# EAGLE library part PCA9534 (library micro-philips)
8-bit I2C-bus and SMBus low power I/O port with interrupt Source: www.nxp.com .. PCA9534_3.pdf
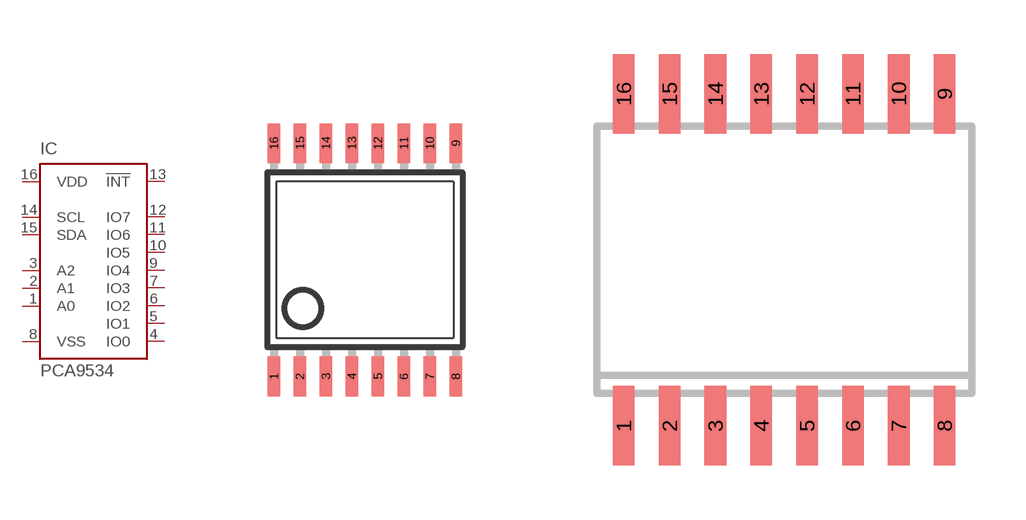
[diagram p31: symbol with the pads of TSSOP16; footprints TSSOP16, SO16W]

Designator prefix IC

## PCA9534PW (MPN: PCA9534PW; OC_FARNELL: 1408285; OC_NEWARK: 18M7516)  [TSSOP16]
1  A0  in
2  A1  in
3  A2  in
4  IO0
5  IO1
6  IO2
7  IO3
8  VSS  pwr
9  IO4
10  IO5
11  IO6
12  IO7
13  !INT  oc
14  SCL  in
15  SDA
16  VDD  pwr

## PCA9534D (MPN: PCA9534DB; OC_FARNELL: 1408284; OC_NEWARK: 18M7513)  [SO16W]
Pads as for TSSOP16

## PCA9534BS (MPN: PCA9534BS,118; OC_FARNELL: unknown; OC_NEWARK: 70R6525)  [HVQFN16_4X4]
1  A2  in
2  IO0
3  IO1
4  IO2
5  IO3
6  VSS  pwr
7  IO4
8  IO5
9  IO6
10  IO7
11  !INT  oc
12  SCL  in
13  SDA
14  VDD  pwr
15  A0  in
16  A1  in

## PCA9534BS3 (MPN: PCA9534BS3,118; OC_FARNELL: unknown; OC_NEWARK: 70R6526)  [HVQFN16_3X3]
Pads as for HVQFN16_4X4

## Footprint TSSOP16 (pad centres in mm)
TSSOP16: plastic thin shrink small outline package; 16 leads; body width 4.4 mm SOT403-1 Source: PCA9534_3.pdf
smd 0.305 x 0.991: 1 -2.275,-2.918; 2 -1.625,-2.918; 3 -0.975,-2.918; 4 -0.325,-2.918; 5 0.325,-2.918; 6 0.975,-2.918; 7 1.625,-2.918; 8 2.275,-2.918; 9 2.275,2.918; 10 1.625,2.918; 11 0.975,2.918; 12 0.325,2.918; 13 -0.325,2.918; 14 -0.975,2.918; 15 -1.625,2.918; 16 -2.275,2.918

## Footprint SO16W (pad centres in mm)
Small Outline Package 7.6 x 10.6 mm
smd 0.6 x 2.2: 1 -4.445,-4.6; 2 -3.175,-4.6; 3 -1.905,-4.6; 4 -0.635,-4.6; 5 0.635,-4.6; 6 1.905,-4.6; 7 3.175,-4.6; 8 4.445,-4.6; 9 4.445,4.6; 10 3.175,4.6; 11 1.905,4.6; 12 0.635,4.6; 13 -0.635,4.6; 14 -1.905,4.6; 15 -3.175,4.6; 16 -4.445,4.6

## Footprint HVQFN16_4X4 (pad centres in mm)
HVQFN16: plastic thermal enhanced very thin quad flat package; no leads; 16 terminals; body 4 x 4 x 0.85 mm SOT629-1 Source: PCA9534_3.pdf
smd 0.5 x 0.3: 1 -1.8,0.975; 2 -1.8,0.325; 3 -1.8,-0.325; 4 -1.8,-0.975; 9 1.8,-0.975; 10 1.8,-0.325; 11 1.8,0.325; 12 1.8,0.975
smd 0.3 x 0.5: 5 -0.975,-1.8; 6 -0.325,-1.8; 7 0.325,-1.8; 8 0.975,-1.8; 13 0.975,1.8; 14 0.325,1.8; 15 -0.325,1.8; 16 -0.975,1.8
smd 2.25 x 2.25: TH 0,0

## Footprint HVQFN16_3X3 (pad centres in mm)
HVQFN16: plastic thermal enhanced very thin quad flat package; no leads; 16 terminals; body 3 x 3 x 0.85 mm SOT758-1 Source: PCA9534_3.pdf
smd 0.5 x 0.3: 1 -1.25,0.75; 2 -1.25,0.25; 3 -1.25,-0.25; 4 -1.25,-0.75; 9 1.25,-0.75; 10 1.25,-0.25; 11 1.25,0.25; 12 1.25,0.75
smd 0.3 x 0.5: 5 -0.75,-1.25; 6 -0.25,-1.25; 7 0.25,-1.25; 8 0.75,-1.25; 13 0.75,1.25; 14 0.25,1.25; 15 -0.25,1.25; 16 -0.75,1.25
smd 1.75 x 1.75: TH 0,0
